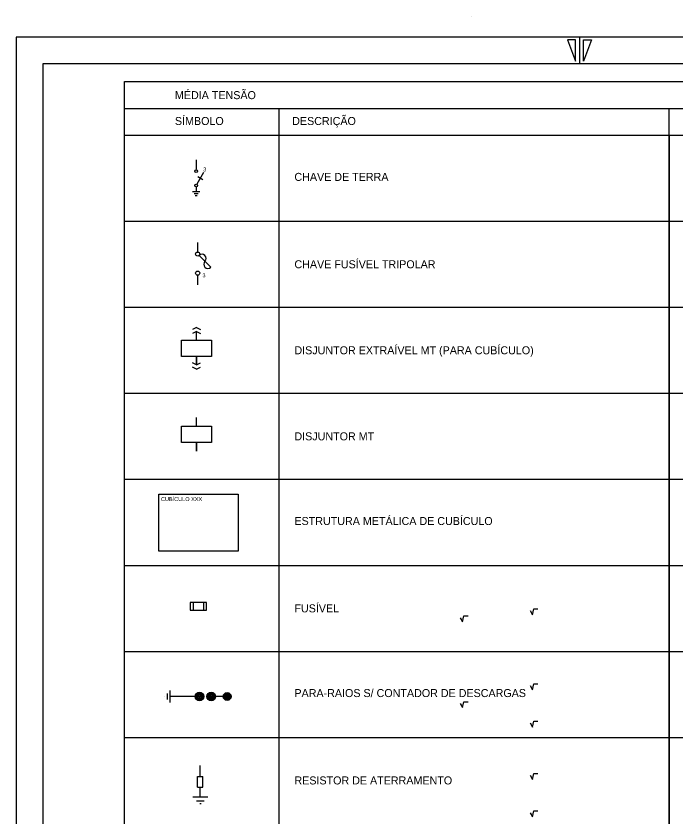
# Model space of a CAD drawing. Extents: x 563 to 3226, y 358 to 960.
# Drawn here: x 1473.9 to 1721, y 659.8 to 959.9 of the extents above; entities that cross this region are included whole.
import ezdxf

# ---------------------------------------------------------------- set-up
doc = ezdxf.new("R2010")
doc.units = 0
for name, color, linetype in [('13', 7, 'Continuous'), ('Default', 7, 'Continuous'), ('New Level (0)', 7, 'Continuous')]:
    doc.layers.add(name, color=color, linetype=linetype)

# ---------------------------------------------------------------- blocks, each defined once
blk = doc.blocks.new('POINT_DISPLAY')
at = {"layer": 'Default'}
blk.add_line((0, 0), (0, 0), dxfattribs=at)
blk = doc.blocks.new('_U4')
at = {"layer": 'Default'}
for p, q in [((-1.47, 0.42), (-0.62, -1.12)), ((-0.62, -1.12), (-0.07, 1.12)), ((-0.07, 1.12), (1.47, 1.12))]:
    blk.add_line(p, q, dxfattribs=at)

msp = doc.modelspace()

# ---------------------------------------------------------------- linework, layer by layer
at = {"layer": '13'}
for points in [[(1541.44, 843.24), (1539.91, 842.48)], [(1541.44, 843.24), (1542.96, 842.48)], [(1541.44, 841.71), (1539.91, 840.95)], [(1541.44, 841.71), (1542.96, 840.95)], [(1541.44, 829.14), (1539.91, 829.91)], [(1541.44, 827.62), (1539.91, 828.38)], [(1541.44, 829.14), (1542.96, 829.91)], [(1541.44, 827.62), (1542.96, 828.38)]]:
    msp.add_lwpolyline(points, dxfattribs=at)
at = {"layer": 'Default'}
for p, q in [((1541.34, 905.95), (1541.34, 902.31)), ((1544.14, 901.25), (1541.61, 896.86)), ((1543.79, 898.52), (1541.96, 899.58)), ((1541.34, 895.78), (1541.34, 894.03)), ((1542.75, 894.03), (1539.93, 894.03)), ((1540.64, 893.32), (1542.05, 893.32)), ((1540.99, 892.62), (1541.69, 892.62)), ((1546.83, 865.77), (1542.46, 870.15)), ((1541.44, 838.49), (1541.44, 841.71)), ((1541.44, 838.49), (1541.44, 841.71)), ((1535.82, 838.49), (1547.06, 838.49)), ((1535.82, 832.37), (1535.82, 838.49)), ((1536.32, 838.49), (1546.56, 838.49)), ((1547.06, 838.49), (1547.06, 832.37)), ((1547.06, 832.37), (1535.82, 832.37)), ((1541.44, 832.37), (1541.44, 829.14)), ((1541.44, 829.14), (1541.44, 832.37)), ((1541.44, 806.26), (1541.44, 809.48)), ((1541.44, 806.26), (1541.44, 809.48)), ((1535.82, 806.26), (1547.06, 806.26)), ((1535.82, 800.14), (1535.82, 806.26)), ((1536.32, 806.26), (1546.56, 806.26)), ((1547.06, 806.26), (1547.06, 800.14)), ((1547.06, 800.14), (1535.82, 800.14)), ((1541.44, 800.14), (1541.44, 796.91)), ((1541.44, 796.91), (1541.44, 800.14)), ((1540.23, 740.17), (1540.23, 737.24)), ((1544.1, 740.17), (1544.1, 737.24)), ((1530.48, 706.03), (1530.48, 703.83)), ((1531.58, 702.73), (1531.58, 707.13)), ((1529.38, 704.93), (1529.38, 704.93)), ((1538.18, 704.93), (1531.58, 704.93)), ((1542.58, 704.93), (1538.18, 704.93)), ((1552.95, 704.93), (1546.98, 704.93)), ((1542.88, 675.02), (1542.88, 679.06)), ((1541.87, 670.98), (1541.87, 675.02)), ((1541.87, 675.02), (1543.89, 675.02)), ((1543.89, 670.98), (1543.89, 675.02)), ((1541.87, 670.98), (1543.89, 670.98)), ((1542.88, 667.27), (1542.88, 670.98)), ((1545.67, 667.27), (1540.09, 667.27)), ((1541.48, 665.87), (1544.28, 665.87)), ((1543.22, 664.71), (1542.68, 664.71))]:
    msp.add_line(p, q, dxfattribs=at)
for points in [[(1527.34, 780.72), (1557.04, 780.72), (1557.04, 759.43), (1527.34, 759.43)], [(1539.1, 740.17), (1539.1, 737.24), (1545.22, 737.24), (1545.22, 740.17)]]:
    msp.add_lwpolyline(points, close=True, dxfattribs=at)
for centre, radius in [((1541.34, 901.78), 0.528), ((1541.34, 896.4), 0.528), ((1541.91, 870.69), 0.768), ((1541.91, 863.55), 0.768), ((1542.58, 704.93), 1.65), ((1542.58, 704.93), 1.37), ((1542.58, 704.93), 1.1), ((1542.58, 704.93), 0.825), ((1542.58, 704.93), 0.55), ((1542.58, 704.93), 0.275), ((1546.98, 704.93), 1.65), ((1546.98, 704.93), 1.37), ((1546.98, 704.93), 1.1), ((1546.98, 704.93), 0.825), ((1546.98, 704.93), 0.55), ((1546.98, 704.93), 0.275), ((1552.95, 704.93), 1.48), ((1552.95, 704.93), 1.24), ((1552.95, 704.93), 0.99), ((1552.95, 704.93), 0.742), ((1552.95, 704.93), 0.495), ((1552.95, 704.93), 0.247)]:
    msp.add_circle(centre, radius, dxfattribs=at)
at = {"layer": 'New Level (0)'}
for p, q in [((1473.88, 951.96), (1473.88, 357.96)), ((2314.88, 951.96), (1473.88, 951.96)), ((2314.88, 951.96), (1473.88, 951.96)), ((1473.88, 951.96), (1473.88, 357.96)), ((1684.88, 951.96), (1684.88, 941.96)), ((1683.38, 950.96), (1680.38, 950.96)), ((1680.38, 950.96), (1683.38, 942.96)), ((1683.38, 942.96), (1683.38, 950.96)), ((1686.38, 942.96), (1686.38, 950.96)), ((1686.38, 950.96), (1689.38, 950.96)), ((1689.38, 950.96), (1686.38, 942.96)), ((1483.88, 941.96), (1483.88, 367.96)), ((2304.88, 941.96), (1483.88, 941.96)), ((1483.88, 941.96), (1483.88, 367.96)), ((1514.44, 915.21), (1514.44, 935.35)), ((1514.44, 935.35), (2214.61, 935.35)), ((1514.44, 925.28), (1886.12, 925.28)), ((1572.28, 925.28), (1572.28, 429.83)), ((1718.4, 915.21), (1718.4, 925.28)), ((1514.44, 882.98), (2214.61, 882.98)), ((1541.91, 871.46), (1541.91, 875.02)), ((1541.91, 859.21), (1541.91, 862.78)), ((1514.44, 850.75), (2214.61, 850.75)), ((1514.44, 818.53), (2214.61, 818.53)), ((1514.44, 786.3), (1864.53, 786.3)), ((1514.44, 754.07), (2214.61, 754.07)), ((1514.44, 721.84), (1864.53, 721.84)), ((1514.44, 689.61), (2214.61, 689.61))]:
    msp.add_line(p, q, dxfattribs=at)
for points in [[(1514.44, 915.21), (1718.4, 915.21), (1718.4, 429.83), (1514.44, 429.83)], [(1718.4, 915.21), (1864.53, 915.21), (1864.53, 429.83), (1718.4, 429.83)]]:
    msp.add_lwpolyline(points, close=True, dxfattribs=at)
for centre, start, end in [((1543.52, 869.08), 315, 133.4107), ((1545.73, 866.87), 135, 315)]:
    msp.add_arc(centre, 1.56, start, end, dxfattribs=at)

# ---------------------------------------------------------------- block references
at = {"layer": 'Default'}
for name, p in [('POINT_DISPLAY', (1644.38, 959.87)), ('_U4', (1641.67, 734.05)), ('_U4', (1667.84, 736.68)), ('_U4', (1667.84, 708.6)), ('_U4', (1641.67, 701.88)), ('_U4', (1667.84, 694.62)), ('_U4', (1667.84, 674.99)), ('_U4', (1667.84, 661))]:
    msp.add_blockref(name, p, dxfattribs=at)

# ---------------------------------------------------------------- texts
for s, height, p in [('MÉDIA TENSÃO', 3, (1533.38, 928.73)), ('SÍMBOLO', 3, (1533.38, 919.04)), ('DESCRIÇÃO', 3, (1577.29, 919.04)), ('3', 1.5, (1543.99, 901.63)), ('CHAVE DE TERRA', 3, (1578.13, 898.1)), ('CHAVE FUSÍVEL TRIPOLAR', 3, (1578.13, 865.37)), ('3', 1.5, (1543.69, 862)), ('DISJUNTOR EXTRAÍVEL MT (PARA CUBÍCULO)', 3, (1578.13, 833.14)), ('DISJUNTOR MT', 3, (1578.13, 800.91)), ('CUBÍCULO XXX', 1.5, (1528.16, 778.15)), ('ESTRUTURA METÁLICA DE CUBÍCULO', 3, (1578.13, 769.18)), ('FUSÍVEL', 3, (1578.13, 736.46)), ('PARA-RAIOS S/ CONTADOR DE DESCARGAS', 3, (1578.13, 704.73)), ('RESISTOR DE ATERRAMENTO', 3, (1578.13, 672))]:
    msp.add_text(s, height=height, dxfattribs=at).set_placement(p)

doc.saveas('drawing.dxf')
